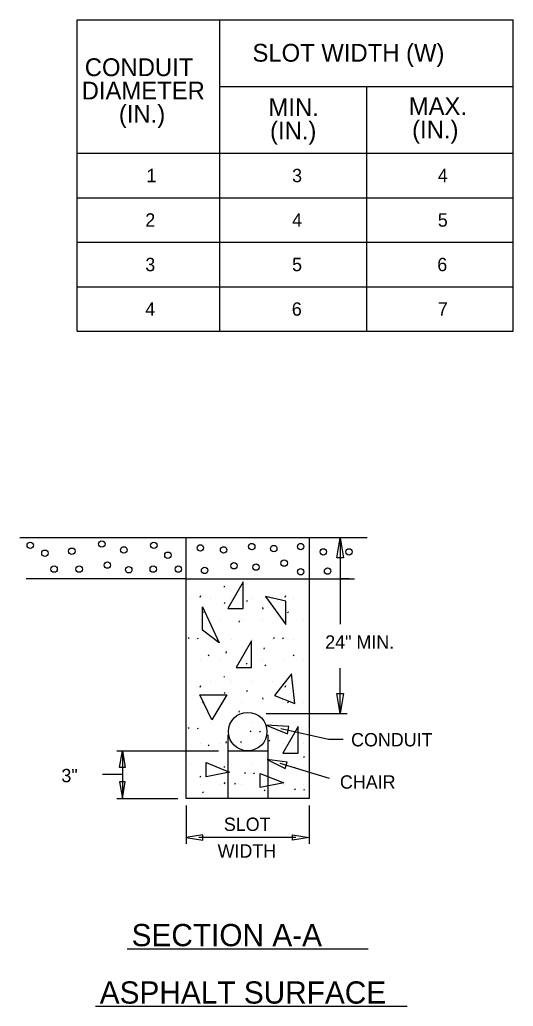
# Model space of a CAD drawing. Extents: x -234.3 to -227.16, y 225.75 to 234.94.
# Drawn here: x -229.984 to -227.769, y 230.419 to 234.853 of the extents above; entities that cross this region are included whole.
import ezdxf

# ---------------------------------------------------------------- set-up
doc = ezdxf.new("R2010")
doc.units = 0
for name, color, linetype in [('Default', 7, 'Continuous'), ('DETL-DIMS', 7, 'Continuous'), ('DETL-LINE', 7, 'Continuous'), ('DETL-NOTE', 7, 'Continuous'), ('DETL-PATT', 7, 'Continuous'), ('DETL-TITL', 7, 'Continuous')]:
    doc.layers.add(name, color=color, linetype=linetype)

msp = doc.modelspace()

# ---------------------------------------------------------------- linework, layer by layer
at = {"layer": 'Default'}
for p, q in [((-229.0678, 232.3065), (-229.065, 232.3022)), ((-228.6852, 232.3065), (-228.685, 232.3062)), ((-229.1748, 232.2582), (-229.1719, 232.2647)), ((-229.0655, 232.2287), (-229.0626, 232.2352)), ((-228.9657, 232.2426), (-228.9628, 232.2383)), ((-228.7922, 232.2582), (-228.7893, 232.2647)), ((-229.1643, 232.1916), (-229.1615, 232.1872)), ((-228.8945, 232.2106), (-228.8937, 232.2042)), ((-228.7817, 232.1916), (-228.7788, 232.1872)), ((-229, 232.1453), (-228.9971, 232.1517)), ((-229.228, 232.0766), (-229.2251, 232.0722)), ((-229.187, 232.0749), (-229.1842, 232.0706)), ((-228.8454, 232.0766), (-228.8425, 232.0722)), ((-228.8044, 232.0749), (-228.8015, 232.0706)), ((-229.0583, 232.0067), (-229.0554, 232.0132)), ((-228.8878, 232.0232), (-228.8849, 232.0297)), ((-229.1388, 231.9983), (-229.1359, 231.994)), ((-228.7562, 231.9983), (-228.7533, 231.994)), ((-228.9684, 231.9607), (-228.9655, 231.9563)), ((-228.8834, 231.9529), (-228.8805, 231.9486)), ((-229.0678, 231.9018), (-229.065, 231.8975)), ((-228.6852, 231.9018), (-228.685, 231.9015)), ((-229.1748, 231.8535), (-229.1719, 231.86)), ((-229.0655, 231.824), (-229.0626, 231.8305)), ((-228.9657, 231.8379), (-228.9628, 231.8336)), ((-228.7922, 231.8535), (-228.7893, 231.86)), ((-229.1643, 231.7868), (-229.1615, 231.7825)), ((-228.8945, 231.8059), (-228.8937, 231.7995)), ((-228.7817, 231.7868), (-228.7788, 231.7825)), ((-229, 231.7406), (-228.9971, 231.747)), ((-229.228, 231.6718), (-229.2251, 231.6675)), ((-229.187, 231.6702), (-229.1842, 231.6659)), ((-228.9496, 231.6574), (-228.9467, 231.653)), ((-228.9086, 231.6557), (-228.9057, 231.6514)), ((-229.0583, 231.602), (-229.0554, 231.6085)), ((-228.992, 231.604), (-228.9891, 231.6105)), ((-228.865, 231.61), (-228.8621, 231.6165)), ((-229.1388, 231.5936), (-229.1359, 231.5893)), ((-228.7104, 231.5413), (-228.7075, 231.537)), ((-229.0678, 231.4971), (-229.065, 231.4928)), ((-228.7514, 231.4911), (-228.7499, 231.4945)), ((-229.1748, 231.4488), (-229.1719, 231.4552)), ((-228.9756, 231.4702), (-228.9728, 231.4659)), ((-228.9347, 231.4686), (-228.9318, 231.4643)), ((-229.0655, 231.4193), (-229.0626, 231.4257)), ((-229.0181, 231.4169), (-229.0152, 231.4234)), ((-228.8864, 231.392), (-228.8835, 231.3877)), ((-228.7506, 231.3968), (-228.7478, 231.3925)), ((-228.7097, 231.3952), (-228.7068, 231.3909)), ((-229.1643, 231.3821), (-229.1615, 231.3778))]:
    msp.add_line(p, q, dxfattribs=at)
at = {"layer": 'DETL-DIMS'}
for p, q in [((-228.546, 232.525), (-228.546, 232.136)), ((-228.546, 231.735), (-228.546, 231.939)), ((-228.878, 231.735), (-228.515, 231.735)), ((-228.812, 231.667), (-228.598, 231.62)), ((-228.598, 231.62), (-228.532, 231.62)), ((-229.548, 231.567), (-229.092, 231.567)), ((-229.523, 231.567), (-229.523, 231.353)), ((-228.817, 231.511), (-228.596, 231.444)), ((-229.523, 231.46), (-229.612, 231.46)), ((-229.548, 231.353), (-229.274, 231.353)), ((-229.237, 231.322), (-229.237, 231.149)), ((-228.685, 231.322), (-228.685, 231.149)), ((-228.745, 231.177), (-229.18, 231.177))]:
    msp.add_line(p, q, dxfattribs=at)
for points in [[(-228.531, 232.435), (-228.561, 232.435), (-228.546, 232.525)], [(-228.561, 231.825), (-228.531, 231.825), (-228.546, 231.735)], [(-228.783, 231.644), (-228.776, 231.676), (-228.878, 231.682)], [(-229.511, 231.492), (-229.536, 231.492), (-229.523, 231.567)], [(-228.793, 231.488), (-228.784, 231.516), (-228.874, 231.528)], [(-229.511, 231.428), (-229.536, 231.428), (-229.523, 231.353)], [(-229.162, 231.165), (-229.162, 231.19), (-229.237, 231.177)], [(-228.76, 231.165), (-228.76, 231.19), (-228.685, 231.177)]]:
    msp.add_lwpolyline(points, close=True, dxfattribs=at)
at = {"layer": 'DETL-LINE'}
for p, q in [((-228.425, 232.525), (-229.984, 232.525)), ((-229.237, 232.34), (-229.237, 232.525)), ((-228.685, 232.525), (-228.685, 232.34)), ((-229.237, 232.34), (-229.955, 232.34)), ((-229.237, 232.34), (-228.685, 232.34)), ((-229.237, 231.353), (-229.237, 232.34)), ((-228.685, 232.34), (-228.481, 232.34)), ((-228.685, 232.34), (-228.685, 231.353)), ((-228.506, 232.34), (-228.544, 232.34)), ((-229.05, 231.639), (-229.05, 231.354)), ((-228.871, 231.639), (-228.871, 231.354)), ((-229.05, 231.567), (-228.871, 231.567)), ((-228.895, 231.6), (-228.895, 231.6)), ((-228.685, 231.353), (-229.237, 231.353))]:
    msp.add_line(p, q, dxfattribs=at)
msp.add_circle((-228.9608, 231.6535), 0.0864, dxfattribs=at)
at = {"layer": 'DETL-NOTE'}
for p, q in [((-229.7262, 234.8526), (-227.7692, 234.8526)), ((-229.7262, 233.4526), (-229.7262, 234.8526)), ((-229.0862, 233.4526), (-229.0862, 234.8526)), ((-227.7692, 233.4526), (-227.7692, 234.8526)), ((-229.0862, 234.5526), (-227.7692, 234.5526)), ((-228.4272, 234.5526), (-228.4272, 233.4526)), ((-229.7262, 234.2526), (-227.7692, 234.2526)), ((-229.7262, 234.0526), (-227.7692, 234.0526)), ((-229.7262, 233.8526), (-227.7692, 233.8526)), ((-229.7262, 233.6526), (-227.7692, 233.6526)), ((-229.7262, 233.4526), (-227.7692, 233.4526))]:
    msp.add_line(p, q, dxfattribs=at)
at = {"layer": 'DETL-PATT'}
for p, q in [((-228.981, 232.326), (-229.05, 232.206)), ((-228.981, 232.206), (-228.981, 232.326)), ((-229.221, 232.252), (-229.221, 232.252)), ((-229.128, 232.252), (-229.128, 232.252)), ((-229.035, 232.252), (-229.035, 232.252)), ((-228.942, 232.252), (-228.942, 232.252)), ((-228.79, 232.24), (-228.881, 232.261)), ((-228.881, 232.261), (-228.79, 232.135)), ((-228.849, 232.252), (-228.849, 232.252)), ((-228.79, 232.135), (-228.79, 232.24)), ((-228.755, 232.252), (-228.755, 232.252)), ((-229.164, 232.214), (-229.089, 232.053)), ((-229.164, 232.109), (-229.164, 232.214)), ((-229.05, 232.206), (-228.981, 232.206)), ((-229.175, 232.159), (-229.175, 232.159)), ((-229.082, 232.159), (-229.082, 232.159)), ((-228.988, 232.159), (-228.988, 232.159)), ((-228.895, 232.159), (-228.895, 232.159)), ((-228.802, 232.159), (-228.802, 232.159)), ((-228.709, 232.159), (-228.709, 232.159)), ((-229.089, 232.053), (-229.164, 232.109)), ((-229.221, 232.066), (-229.221, 232.066)), ((-229.128, 232.066), (-229.128, 232.066)), ((-229.035, 232.066), (-229.035, 232.066)), ((-228.944, 232.062), (-229.012, 231.942)), ((-228.944, 231.942), (-228.944, 232.062)), ((-228.942, 232.066), (-228.942, 232.066)), ((-228.849, 232.066), (-228.849, 232.066)), ((-228.755, 232.066), (-228.755, 232.066)), ((-229.175, 231.973), (-229.175, 231.973)), ((-229.082, 231.973), (-229.082, 231.973)), ((-228.988, 231.973), (-228.988, 231.973)), ((-228.895, 231.973), (-228.895, 231.973)), ((-228.802, 231.973), (-228.802, 231.973)), ((-228.709, 231.973), (-228.709, 231.973)), ((-229.012, 231.942), (-228.944, 231.942)), ((-229.221, 231.88), (-229.221, 231.88)), ((-229.128, 231.88), (-229.128, 231.88)), ((-229.035, 231.88), (-229.035, 231.88)), ((-228.942, 231.88), (-228.942, 231.88)), ((-228.849, 231.88), (-228.849, 231.88)), ((-228.764, 231.913), (-228.84, 231.815)), ((-228.749, 231.78), (-228.764, 231.913)), ((-228.755, 231.88), (-228.755, 231.88)), ((-229.122, 231.707), (-229.176, 231.819)), ((-229.176, 231.819), (-229.054, 231.819)), ((-229.175, 231.786), (-229.175, 231.786)), ((-229.054, 231.819), (-229.122, 231.707)), ((-229.082, 231.786), (-229.082, 231.786)), ((-228.988, 231.786), (-228.988, 231.786)), ((-228.895, 231.786), (-228.895, 231.786)), ((-228.84, 231.815), (-228.749, 231.78)), ((-228.802, 231.786), (-228.802, 231.786)), ((-228.709, 231.786), (-228.709, 231.786)), ((-229.221, 231.693), (-229.221, 231.693)), ((-229.128, 231.693), (-229.128, 231.693)), ((-229.035, 231.693), (-229.035, 231.693)), ((-228.942, 231.693), (-228.942, 231.693)), ((-228.849, 231.693), (-228.849, 231.693)), ((-228.734, 231.677), (-228.803, 231.557)), ((-228.755, 231.693), (-228.755, 231.693)), ((-228.734, 231.557), (-228.734, 231.677)), ((-229.175, 231.6), (-229.175, 231.6)), ((-229.082, 231.6), (-229.082, 231.6)), ((-228.988, 231.6), (-228.988, 231.6)), ((-228.802, 231.6), (-228.802, 231.6)), ((-228.709, 231.6), (-228.709, 231.6)), ((-228.803, 231.557), (-228.734, 231.557)), ((-229.221, 231.507), (-229.221, 231.507)), ((-229.148, 231.45), (-229.148, 231.514)), ((-229.148, 231.514), (-229.042, 231.471)), ((-229.128, 231.507), (-229.128, 231.507)), ((-229.035, 231.507), (-229.035, 231.507)), ((-228.942, 231.507), (-228.942, 231.507)), ((-228.849, 231.507), (-228.849, 231.507)), ((-228.755, 231.507), (-228.755, 231.507)), ((-229.042, 231.471), (-229.148, 231.45)), ((-228.905, 231.465), (-228.799, 231.423)), ((-228.905, 231.402), (-228.905, 231.465)), ((-229.175, 231.414), (-229.175, 231.414)), ((-229.082, 231.414), (-229.082, 231.414)), ((-228.988, 231.414), (-228.988, 231.414)), ((-228.799, 231.423), (-228.905, 231.402)), ((-228.895, 231.414), (-228.895, 231.414)), ((-228.802, 231.414), (-228.802, 231.414)), ((-228.709, 231.414), (-228.709, 231.414))]:
    msp.add_line(p, q, dxfattribs=at)
for centre in [(-229.9369, 232.4907), (-229.6156, 232.4967), (-229.3822, 232.4907), (-228.9428, 232.4848), (-228.7232, 232.4848), (-229.871, 232.4551), (-229.7502, 232.464), (-229.5168, 232.4699), (-229.3191, 232.4462), (-229.1735, 232.4788), (-229.0691, 232.4699), (-228.844, 232.4759), (-228.6216, 232.461), (-228.5062, 232.461), (-229.5909, 232.4017), (-229.0225, 232.3987), (-228.9236, 232.3928), (-228.7973, 232.4106), (-229.8298, 232.3838), (-229.7172, 232.3838), (-229.4948, 232.3809), (-229.3849, 232.3838), (-229.2724, 232.3838), (-229.1543, 232.3779), (-228.7232, 232.372), (-228.6023, 232.3749)]:
    msp.add_circle(centre, 0.0144, dxfattribs=at)
msp.add_arc((-229.2369, 231.354), 0.000373, 180, 270, dxfattribs=at)
at = {"layer": 'DETL-TITL'}
for p, q in [((-229.5015, 230.6778), (-228.4207, 230.6778)), ((-229.644, 230.4191), (-228.2453, 230.4191))]:
    msp.add_line(p, q, dxfattribs=at)

# ---------------------------------------------------------------- texts
at = {"layer": 'DETL-NOTE'}
for s, height, p in [('SLOT WIDTH (W)', 0.08, (-228.9396, 234.6641)), ('CONDUIT', 0.08, (-229.6922, 234.5992)), ('DIAMETER', 0.08, (-229.7061, 234.4943)), ('MIN.', 0.08, (-228.8675, 234.4194)), ('MAX.', 0.08, (-228.2382, 234.4244)), ('(IN.)', 0.08, (-229.5392, 234.3894)), ('(IN.)', 0.08, (-228.223, 234.3195)), ('(IN.)', 0.08, (-228.8607, 234.3145)), ('1', 0.06, (-229.4154, 234.1226)), ('3', 0.06, (-228.7617, 234.1226)), ('4', 0.06, (-228.1078, 234.1226)), ('2', 0.06, (-229.4206, 233.9226)), ('4', 0.06, (-228.7617, 233.9226)), ('5', 0.06, (-228.1079, 233.9226)), ('3', 0.06, (-229.4206, 233.7226)), ('5', 0.06, (-228.7618, 233.7226)), ('6', 0.06, (-228.11, 233.7226)), ('4', 0.06, (-229.4206, 233.5226)), ('6', 0.06, (-228.7629, 233.5226)), ('7', 0.06, (-228.1078, 233.5226)), ('24" MIN.', 0.06, (-228.613, 232.026)), ('CONDUIT', 0.06, (-228.497, 231.587)), ('3"', 0.06, (-229.797, 231.426)), ('CHAIR', 0.06, (-228.547, 231.397)), ('SLOT', 0.06, (-229.068, 231.207)), ('WIDTH', 0.06, (-229.096, 231.087))]:
    msp.add_text(s, height=height, dxfattribs=at).set_placement(p)
at = {"layer": 'DETL-TITL'}
for s, p in [('SECTION A-A', (-229.482, 230.689)), ('ASPHALT SURFACE', (-229.625, 230.431))]:
    msp.add_text(s, height=0.100002, dxfattribs=at).set_placement(p)

doc.saveas('drawing.dxf')
